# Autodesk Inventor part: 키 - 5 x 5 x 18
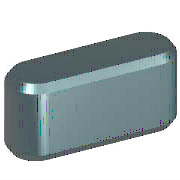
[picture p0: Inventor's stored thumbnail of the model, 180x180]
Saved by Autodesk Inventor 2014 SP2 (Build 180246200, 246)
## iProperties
Created: 2012-02
Part Number: 키 - 5 x 5 x 18
Material: 강철, 연강
Description: 키 및 해당 키홈
Document SubType Name: Modeling
Standard: KS B 1311
Designer: mduedu
Standards Organization: KS
Language: ko-KR
Size Designation: 5 x 5 x 18
Categories: <MemberInstance><Categories><Category DisplayName="샤프트 부품" InternalName="7f7aeb1f-a693-4053-b835-cee3144e0d98" Mnemonic="SHFT"><Category DisplayName="키" Interna
Density: 7.86 g/cm^3
Mass: 3.27476 g
Surface Area: 3.57848 cm^2
Volume: 0.416636 cm^3
Appearance: 강철
IsCustomPart: 1
Author: mduedu
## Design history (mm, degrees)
workplane "Work Plane1"
workplane "Work Plane2"
sketch "스케치1"
  geometry: L1 (2.5, 2.5)-(15.5, 2.5); L2 (15.5, -2.5)-(2.5, -2.5); L3 (0, 9.4)-(0, -7.4) reference; L4 (-5, 0)-(30, 0) reference; L5 (18, 0)-(18, 7); A1 r 2.5 centre (2.5, 0) between (2.5, 2.5) and (2.5, -2.5); A2 r 2.5 centre (15.5, 0) between (15.5, -2.5) and (15.5, 2.5)
  constraints: 6 end point, 5 point on circle, 4 tangent, 3 point on line, 2 centre point, 1 horizontal, 1 parallel, 1 perpendicular
  dimensions: "d0" = 2.5 radius of A1 (= 0.5 x PB); "d13" = 2.5 radius of A2 (= 0.5 x PB); "d14" = 18 distance between parallel lines of L5 L3 (= NLG)
extrude "본체1" new body sketch "스케치1" taper "d3" = 0 deg; stored distance "d4" = 10
workplane "Work Plane3"
body "Solid1"
chamfer "모따기1" distance "d8" = 0.4 (= PHH); stored, may be unused: second distance "d9" = 0.4 (= PHH), angle "d15" = 45 deg
other parameters: "d1" = -3 (= -PNT), "d2" = 2 (= PH - PNT), "NLG" = 18 [user parameter; used in 3 equation terms], "PB" = 5 [user parameter; used in 2 equation terms], "PNT" = 3 [user parameter; used in 2 equation terms], "PH" = 5 [user parameter; used in 1 equation term], "PHH" = 0.4 [user parameter; used in 2 equation terms], "d10" = 0, "d16" = 0, "d17" = 0, "d18" = 0, "WDMIN" = 12 [user parameter], "PLB2" = 18 (= NLG) [user parameter], "WDMAX" = 17 [user parameter], "PLB1" = 18 (= NLG) [user parameter], "RR" = 0.16 [user parameter], "PUEB" = 2.3 [user parameter]
